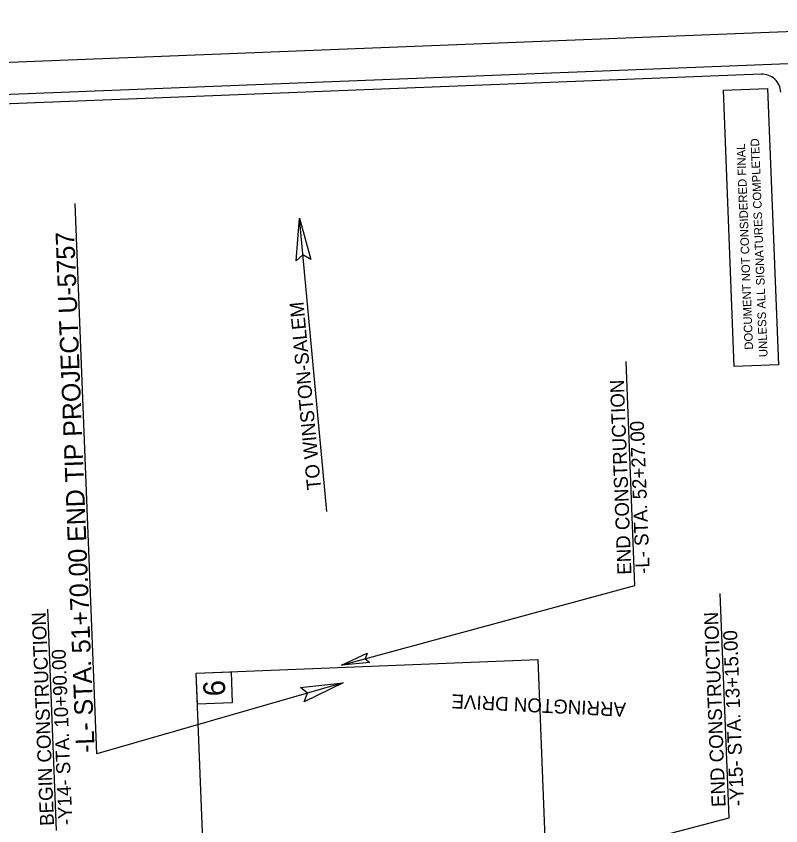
# Model space of a CAD drawing. Extents: x 1624323 to 1631382, y 753034 to 769560.
# Drawn here: x 1627225 to 1629687, y 765176 to 767782 of the extents above; entities that cross this region are included whole.
import ezdxf

# ---------------------------------------------------------------- set-up
doc = ezdxf.new("R2010")
doc.units = 0
for name, color, linetype in [('Old_Level_1', 7, 'Continuous'), ('Prop Dimension', 7, 'Continuous'), ('Prop DSN Text', 7, 'Continuous'), ('Prop Terminator CELL', 7, 'Continuous'), ('Sheet Plot Border Outside CELL', 7, 'Continuous'), ('Sheet Sticker Exception Certification CELL', 7, 'Continuous'), ('Sheet Title CELL', 7, 'Continuous')]:
    doc.layers.add(name, color=color, linetype=linetype)

msp = doc.modelspace()

# ---------------------------------------------------------------- linework, layer by layer
at = {"layer": 'Old_Level_1'}
for points in [[(1627871.9, 763968.6), (1627804.9, 765667.2), (1628904.1, 765710.6), (1628971.1, 764011.9)], [(1627808.5, 765567.3), (1627804.9, 765667.2), (1627917.3, 765671.3), (1627921, 765571.3)]]:
    msp.add_lwpolyline(points, close=True, dxfattribs=at)
at = {"layer": 'Prop Dimension'}
for p, q in [((1627485.3, 765407.8), (1627415.5, 767179.5)), ((1629217.2, 765949), (1629188.7, 766671)), ((1628272.4, 765692.4), (1629217.2, 765949)), ((1629520.3, 765201.3), (1629491.9, 765923.3)), ((1627355.4, 765160.5), (1627327.3, 765873.3)), ((1628277.7, 765635.6), (1627485.3, 765407.8)), ((1628685.4, 764982.9), (1629520.3, 765201.3))]:
    msp.add_line(p, q, dxfattribs=at)
at = {"layer": 'Prop DSN Text'}
msp.add_line((1628225.7, 766188.1), (1628136.8, 767131.8), dxfattribs=at)
at = {"layer": 'Prop Terminator CELL'}
for points in [[(1628126.3, 766995.2), (1628136.8, 767131.8), (1628173.4, 766998.9), (1628147.9, 767013.8)], [(1628363.3, 765701), (1628272.4, 765692.4), (1628355.5, 765731.5), (1628348.6, 765713.1)], [(1628140.3, 765620.5), (1628277.7, 765635.6), (1628152.7, 765574.5), (1628162.8, 765602.6)]]:
    msp.add_lwpolyline(points, close=True, dxfattribs=at)
at = {"layer": 'Sheet Plot Border Outside CELL'}
msp.add_lwpolyline([(1624322.9, 767519.9), (1624724.8, 757327.8), (1631382.3, 757590.3), (1630980.3, 767782.4)], close=True, dxfattribs=at)
at = {"layer": 'Sheet Sticker Exception Certification CELL'}
for p, q in [((1629501.9, 767544.5), (1629644.1, 767550.1)), ((1629644, 767550.1), (1629679.1, 766660.4)), ((1629536.9, 766654.8), (1629501.8, 767544.5)), ((1629679.1, 766660.4), (1629536.9, 766654.8))]:
    msp.add_line(p, q, dxfattribs=at)
at = {"layer": 'Sheet Title CELL'}
for points in [[(1630772.6, 767671.2), (1624538.8, 767425.4)], [(1629623.9, 767595.6), (1624570.2, 767396.3)]]:
    msp.add_lwpolyline(points, dxfattribs=at)
msp.add_arc((1629625.9, 767535.1), 60.6, 2.2582, 92.2582, dxfattribs=at)

# ---------------------------------------------------------------- texts
at = {"layer": 'Prop DSN Text'}
for s, height, rotation, p in [('-L- STA. 51+70.00 END TIP PROJECT U-5757', 60, 92.2582, (1627477.9, 765411.6)), ('TO WINSTON-SALEM', 45, 95.3797, (1628206.9, 766259)), ('END CONSTRUCTION', 45, 92.2582, (1629206, 765984.9)), ('-L- STA. 52+27.00', 45, 92.2582, (1629264.9, 765987.3)), ('BEGIN CONSTRUCTION', 45, 92.2582, (1627347.3, 765176.3)), ('END CONSTRUCTION', 45, 92.2582, (1629509.1, 765237.2)), ('-Y15- STA. 13+15.00', 45, 92.2582, (1629568.1, 765239.6)), ('-Y14- STA. 10+90.00', 45, 92.2582, (1627406.3, 765178.7)), ('6', 70, 92.0586, (1627898.7, 765593.8)), ('ARRINGTON DRIVE', 45, 177.1852, (1629189, 765571.5))]:
    msp.add_text(s, height=height, rotation=rotation, dxfattribs=at).set_placement(p)
at = {"layer": 'Sheet Sticker Exception Certification CELL'}
for s, p in [('DOCUMENT NOT CONSIDERED FINAL', (1629597.5, 766709)), ('UNLESS ALL SIGNATURES COMPLETED', (1629644.1, 766685.3))]:
    msp.add_text(s, height=27.257, rotation=92.2582, dxfattribs=at).set_placement(p)

doc.saveas('drawing.dxf')
